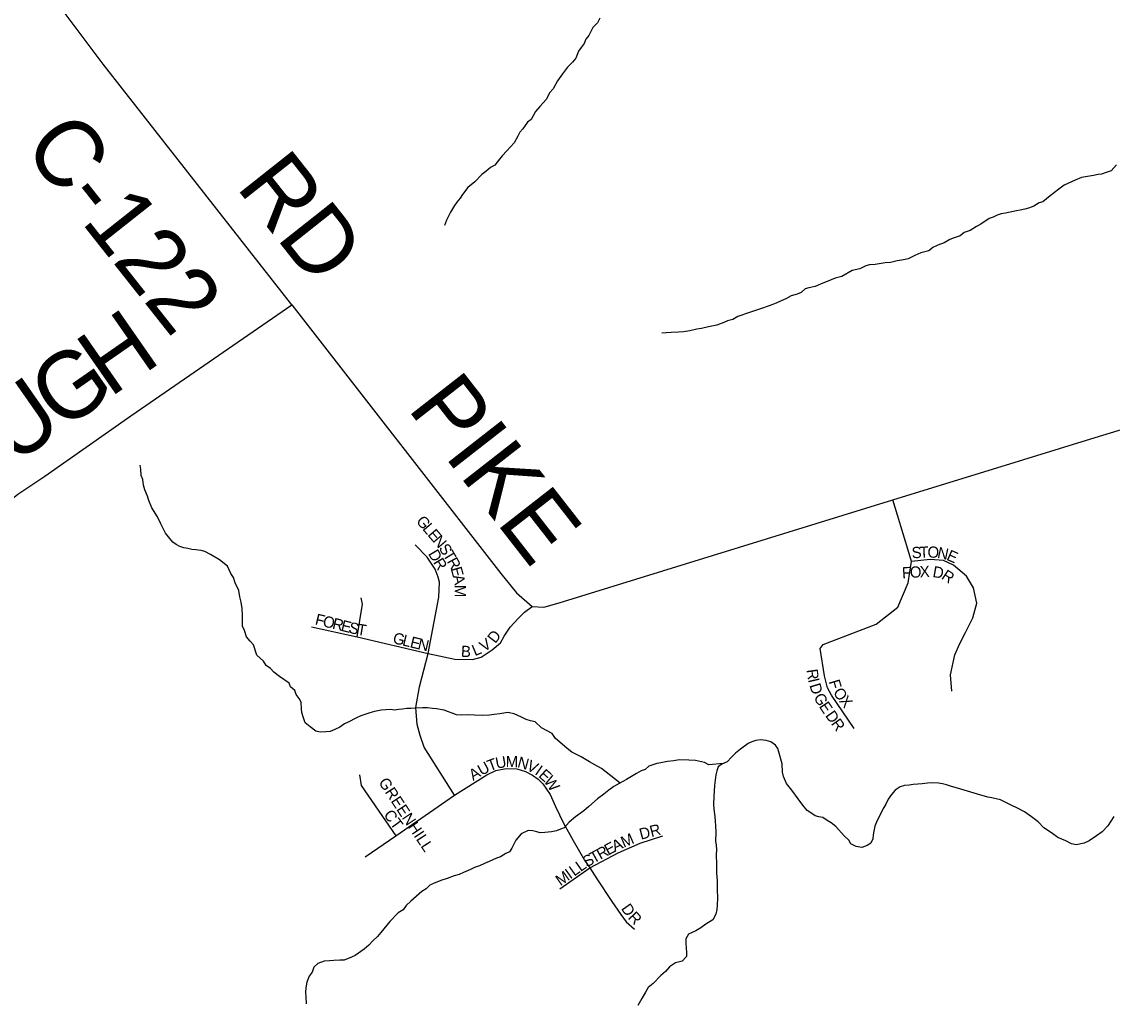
# Model space of a CAD drawing. Extents: x 1310247 to 1664935, y 235267 to 584339.
# Drawn here: x 1481596 to 1486473, y 391172 to 395560 of the extents above; entities that cross this region are included whole.
import ezdxf

# ---------------------------------------------------------------- set-up
doc = ezdxf.new("R2010")
doc.units = 0
for name, color, linetype in [('GM_X_County_Road', 7, 'Continuous'), ('GM_X_County_Road_Text', 7, 'Continuous'), ('GM_X_Minor_River', 7, 'Continuous'), ('GM_X_Township_Subdivision', 7, 'Continuous'), ('GM_X_Township_Subdivision_Text', 7, 'Continuous')]:
    doc.layers.add(name, color=color, linetype=linetype)

msp = doc.modelspace()

# ---------------------------------------------------------------- linework, layer by layer
at = {"layer": 'GM_X_County_Road'}
for points in [[(1482804.2, 394294.3), (1481959.6, 395370.7), (1480701.4, 397047.3), (1480675.9, 397086.6)], [(1479871.9, 391165.9), (1479912.2, 391215.7), (1479964.2, 391283.9), (1480390, 391862.6), (1480465.6, 391986.3), (1481093.8, 392839.4), (1481346.3, 393181.8), (1481456.2, 393329.1), (1481477.1, 393360.6), (1481522.2, 393401.5), (1481577.5, 393448.1), (1481699.6, 393529), (1482082.9, 393797.4), (1482804.2, 394294.3), (1483738.8, 393093.4), (1483807.8, 393007.3), (1483879.1, 392945.3), (1483931, 392942), (1483999.6, 392962.2), (1485491.8, 393422.4), (1486077.3, 393602.9), (1486397.1, 393700.6), (1486533.1, 393742.7)]]:
    msp.add_lwpolyline(points, dxfattribs=at)
at = {"layer": 'GM_X_Minor_River'}
for points in [[(1484180.9, 395575.8), (1484170.5, 395555.9), (1484150.1, 395534.2), (1484131.4, 395498.3), (1484119.1, 395482.5), (1484110.8, 395462.6), (1484098.4, 395444.7), (1484086.1, 395428.9), (1484073.5, 395397), (1484059.2, 395379.2), (1484036.7, 395357.5), (1484014.1, 395327.8), (1483991.5, 395296), (1483972.9, 395260.2), (1483956.5, 395242.5), (1483942, 395214.6), (1483913.3, 395181), (1483892.9, 395159.3), (1483874.2, 395123.5), (1483857.9, 395111.7), (1483837.4, 395081.9), (1483823.1, 395066.1), (1483814.7, 395048.2), (1483798.2, 395018.4), (1483781.8, 395000.6), (1483765.5, 394982.8), (1483745, 394961.1), (1483732.7, 394945.3), (1483712.2, 394919.5), (1483691.9, 394907.8), (1483671.6, 394890.1), (1483653.3, 394876.4), (1483622.6, 394844.8), (1483590.1, 394819.3), (1483567.5, 394787.6), (1483556.1, 394771.7), (1483542.3, 394754), (1483530.5, 394738), (1483513.9, 394708.2), (1483503.6, 394690.3), (1483496.1, 394672.6), (1483486.9, 394648.5)], [(1486492.4, 394921.1), (1486467.9, 394893.5), (1486445.7, 394885.8), (1486425.4, 394878.2), (1486409.4, 394876.4), (1486389.2, 394872.8), (1486353, 394867.4), (1486334.9, 394863.7), (1486306.6, 394852.1), (1486258, 394828.9), (1486233.6, 394811.2), (1486195, 394781.8), (1486162.4, 394754.3), (1486146.3, 394750.5), (1486121.9, 394734.9), (1486097.7, 394727.3), (1486081.6, 394721.6), (1486061.4, 394717.9), (1486045.3, 394714.2), (1485995, 394705), (1485976.8, 394701.3), (1485958.7, 394695.6), (1485940.4, 394685.9), (1485922.3, 394680.2), (1485885.7, 394654.7), (1485865.5, 394645), (1485837.1, 394627.5), (1485810.8, 394617.9), (1485792.5, 394602.2), (1485766.3, 394594.6), (1485746.1, 394586.9), (1485721.7, 394571.3), (1485693.5, 394561.8), (1485671.2, 394550.1), (1485652.9, 394536.4), (1485616.6, 394527), (1485590.3, 394515.4), (1485559.9, 394499.8)], [(1485559.9, 394499.8), (1485539.8, 394496.2), (1485511.6, 394490.7), (1485481.4, 394483.1), (1485457.3, 394481.6), (1485439.2, 394479.9), (1485413, 394474.3), (1485386.9, 394472.8), (1485370.7, 394469), (1485344.4, 394455.4), (1485310.2, 394448), (1485263.5, 394420.7), (1485233.3, 394413.2), (1485215.1, 394405.5), (1485168.6, 394386.3), (1485144.4, 394376.6), (1485116.2, 394371.1), (1485100, 394365.4), (1485081.7, 394349.6), (1485063.5, 394341.9), (1485037.3, 394334.3), (1485012.9, 394320.7), (1484992.7, 394313), (1484970.5, 394301.4), (1484938.2, 394289.9), (1484903.8, 394278.5), (1484877.6, 394268.9), (1484833.2, 394253.6), (1484817, 394247.9), (1484798.8, 394242.2), (1484776.5, 394228.5), (1484752.4, 394222.9), (1484736.2, 394215.2), (1484703.9, 394203.7), (1484667.6, 394196.3), (1484635.4, 394188.8), (1484615.2, 394185.2), (1484583, 394177.7), (1484554.8, 394174.2), (1484532.7, 394172.6), (1484500.6, 394171.1), (1484478.5, 394169.5), (1484458.4, 394167.8)], [(1482176.9, 393386.8), (1482163.4, 393419.1), (1482157.7, 393439.3), (1482146.2, 393467.6), (1482140.5, 393487.8), (1482136.9, 393513.9), (1482129.2, 393532.1), (1482127.7, 393560.2), (1482126, 393578.3)], [(1484272.6, 392156.5), (1484188.8, 392221.6), (1484159, 392238.2), (1484135.1, 392250.7), (1484097.4, 392273.4), (1484079.4, 392281.8), (1484055.6, 392294.2), (1484035.8, 392310.6), (1484002.1, 392339.3), (1483982.3, 392355.7), (1483968.6, 392378), (1483920.9, 392403), (1483891.2, 392429.6), (1483871.2, 392433.9), (1483851.2, 392440.3), (1483831.3, 392450.7), (1483797.5, 392465.3), (1483769.5, 392471.8), (1483751.3, 392468.1), (1483733.3, 392466.5), (1483709.1, 392462.9), (1483687, 392459.2), (1483656.8, 392457.8), (1483620.7, 392460.4), (1483590.6, 392460.9), (1483564.5, 392459.4), (1483540.5, 392461.8), (1483520.5, 392468.2), (1483504.6, 392474.5), (1483484.6, 392482.8), (1483450.6, 392487.5), (1483432.5, 392489.8), (1483410.5, 392492.2), (1483388.4, 392492.5), (1483356.3, 392491.1), (1483336.2, 392489.5), (1483318.1, 392489.8), (1483298, 392486.1), (1483281.9, 392484.4), (1483261.8, 392482.7), (1483245.8, 392485), (1483223.7, 392483.4), (1483203.6, 392481.8), (1483173.4, 392476.2), (1483153.2, 392470.6), (1483112.8, 392457.2), (1483092.6, 392447.6), (1483056.1, 392428.1), (1483039.9, 392420.4), (1483017.6, 392406.7), (1482995.4, 392395.1), (1482975.2, 392387.4), (1482955.1, 392385.7), (1482930.9, 392384.2), (1482910.9, 392388.5), (1482885.2, 392407), (1482863.4, 392425.5), (1482853.8, 392451.7), (1482848.1, 392471.9), (1482846.4, 392488), (1482844.9, 392518.1), (1482837.1, 392534.3), (1482823.4, 392552.6), (1482817.6, 392570.8), (1482797.9, 392587.2), (1482792.1, 392603.3), (1482748.4, 392632.2), (1482722.7, 392652.7), (1482708.9, 392669), (1482689, 392681.4), (1482677.3, 392701.7), (1482647.7, 392728.3), (1482632.4, 392774.7), (1482616.6, 392791), (1482600.8, 392809.4), (1482591.3, 392837.7), (1482583.6, 392857.9), (1482582.4, 392906), (1482580.9, 392936.2), (1482577.3, 392964.3), (1482571.7, 392988.5), (1482566.2, 393016.7), (1482550.7, 393051.1), (1482543.1, 393075.3), (1482531.3, 393093.6), (1482515.8, 393126), (1482480.2, 393154.7), (1482440.4, 393177.5), (1482414.5, 393192), (1482398.6, 393196.3), (1482374.5, 393198.7), (1482356.5, 393201), (1482338.5, 393205.3), (1482320.5, 393207.7), (1482302.5, 393214), (1482286.6, 393222.3), (1482270.7, 393232.6), (1482239.3, 393273.3), (1482217.9, 393315.8), (1482202.4, 393346.2), (1482176.9, 393386.8)], [(1486479.6, 392006.9), (1486452.8, 391965.2), (1486428.3, 391937.5), (1486401.9, 391919.9), (1486369.4, 391898.4), (1486347.1, 391886.8), (1486310.9, 391879.4), (1486290.9, 391883.8), (1486265, 391898.3), (1486229.1, 391912.9), (1486201.4, 391933.5), (1486167.6, 391956.2), (1486142, 391982.7), (1486112.2, 392005.3), (1486080.5, 392027.9), (1486048.7, 392044.5), (1486020.8, 392057.1), (1485973, 392082), (1485935, 392090.7), (1485917, 392093), (1485871, 392105.9), (1485795.2, 392129.3), (1485749.2, 392142.1), (1485731.2, 392148.5), (1485713.3, 392152.8), (1485695.2, 392155.1), (1485669.2, 392157.6), (1485647.1, 392156), (1485622.9, 392152.4), (1485602.8, 392150.7), (1485582.7, 392149.1), (1485564.6, 392147.4), (1485544.5, 392145.7), (1485524.3, 392140), (1485502, 392124.4), (1485485.6, 392104.6), (1485471.2, 392084.8), (1485458.8, 392058.9), (1485448.4, 392043), (1485436, 392017.2), (1485421.4, 391989.3), (1485411, 391963.4), (1485406.6, 391941.4), (1485404.3, 391925.4), (1485402, 391907.4), (1485393.6, 391887.4), (1485377.4, 391877.7), (1485353.2, 391868.1), (1485327.1, 391872.5), (1485303.3, 391885), (1485295.5, 391901.2), (1485273.7, 391919.6), (1485236.3, 391962.4), (1485216.5, 391978.9), (1485198.6, 391989.2), (1485178.8, 392001.6), (1485160.8, 392005.9), (1485144.8, 392010.2), (1485124.9, 392022.6), (1485109, 392032.9), (1485089.4, 392057.3), (1485067.8, 392085.8), (1485040.3, 392124.4), (1485016.7, 392155), (1485003.2, 392185.3), (1484997.5, 392205.5), (1484996.1, 392241.6), (1484982.9, 392290), (1484977.2, 392310.2), (1484967.4, 392326.4), (1484945.6, 392340.8), (1484925.6, 392347.2), (1484901.6, 392349.7), (1484879.4, 392346), (1484861.3, 392340.3), (1484845.1, 392332.6)], [(1484845.1, 392332.6), (1484810.5, 392307.1), (1484788.2, 392289.4), (1484769.8, 392271.7), (1484751.4, 392251.9), (1484727.1, 392240.3), (1484710.9, 392228.6), (1484704.5, 392210.6), (1484700.2, 392192.6), (1484693.4, 392144.6), (1484690.6, 392096.5), (1484690, 392062.3), (1484691.6, 392040.2), (1484695.1, 392006), (1484696.8, 391988), (1484698.4, 391963.8), (1484700, 391937.7), (1484699.2, 391895.6), (1484701, 391879.5), (1484702.6, 391857.4), (1484702.2, 391835.3), (1484703.6, 391793.2), (1484702.9, 391753), (1484706.3, 391720.8), (1484705.6, 391676.7), (1484707.1, 391644.6), (1484706.5, 391608.5), (1484704.2, 391590.4), (1484699.8, 391570.4), (1484687.3, 391544.6), (1484654.9, 391525.1), (1484632.5, 391509.4), (1484610.2, 391495.8), (1484577.9, 391480.2), (1484565.5, 391460.4), (1484565.2, 391442.3), (1484566.8, 391418.2), (1484568.5, 391400.1), (1484568.2, 391380.1), (1484549.8, 391360.3), (1484519.5, 391352.8), (1484493.1, 391335.2), (1484474.7, 391313.5), (1484454.3, 391295.8), (1484419.6, 391260.2), (1484397.2, 391242.6), (1484384.8, 391220.7), (1484368.3, 391192.9), (1484351.7, 391161.1)], [(1484733.1, 392243.2), (1484668.8, 392237.3), (1484648.9, 392247.7), (1484608.9, 392256.4), (1484578.9, 392259), (1484536.7, 392259.7), (1484512.6, 392256.1), (1484484.4, 392252.6), (1484454.2, 392247.1), (1484436.1, 392243.4), (1484399.8, 392232), (1484383.5, 392216.2), (1484365.3, 392210.5), (1484345, 392198.8), (1484300.4, 392171.5), (1484268, 392154), (1484243.7, 392140.4), (1484221.3, 392124.7), (1484199, 392107.1), (1484170.5, 392085.5), (1484131.8, 392052), (1484109.4, 392032.4), (1484072.8, 392004.9), (1484044.3, 391981.3), (1484021.8, 391955.6), (1484005.6, 391949.9), (1483987.4, 391942.2), (1483965.3, 391938.5), (1483935.1, 391935.1), (1483915, 391933.4), (1483899, 391937.7), (1483881, 391942), (1483861, 391944.4), (1483828.6, 391928.9), (1483806.1, 391901.2), (1483787.4, 391865.4), (1483777.1, 391849.5), (1483760.9, 391841.8), (1483736.6, 391826.2), (1483718.4, 391820.5), (1483686, 391805), (1483665.8, 391797.3), (1483643.5, 391785.6), (1483621.3, 391778), (1483603.1, 391770.3), (1483570.8, 391756.8), (1483552.6, 391747.1), (1483530.4, 391741.5), (1483498.1, 391730), (1483473.9, 391722.4), (1483439.5, 391708.9), (1483421.3, 391699.2), (1483405, 391683.5), (1483384.7, 391671.8), (1483335.8, 391628.5), (1483315.4, 391608.8), (1483301, 391588.9), (1483278.7, 391575.3), (1483241.9, 391537.8), (1483201, 391488.3), (1483186.6, 391470.5), (1483166.2, 391450.8), (1483147.8, 391431.1), (1483127.4, 391413.4), (1483086.8, 391386), (1483070.6, 391378.2), (1483038.3, 391364.8), (1483018.2, 391365.1), (1482992.1, 391363.5), (1482972, 391361.9), (1482947.9, 391360.3), (1482919.6, 391348.8), (1482901.3, 391333), (1482894.9, 391311.1), (1482880.5, 391293.3), (1482870, 391265.3), (1482865.6, 391241.3), (1482865.3, 391221.3), (1482866.9, 391201.2), (1482868.4, 391169)]]:
    msp.add_lwpolyline(points, dxfattribs=at)
at = {"layer": 'GM_X_Township_Subdivision'}
for points in [[(1485558.7, 393202.5), (1485491.8, 393422.4)], [(1483413.1, 392735.1), (1483460.5, 392986.7), (1483464.7, 393054.8), (1483458.5, 393077.5), (1483444, 393112.5), (1483409, 393166.1), (1483355.4, 393221.8)], [(1485318.3, 392400.3), (1485217.2, 392549.7), (1485199.6, 392582.7), (1485186.4, 392635.4), (1485166.6, 392758.5), (1485179.8, 392776.1), (1485417.2, 392866.2), (1485513.9, 392943.1), (1485560, 393050.8), (1485575.4, 393147.5), (1485558.7, 393202.5)], [(1485755.6, 392567.3), (1485749, 392639.8), (1485768.8, 392729.9), (1485790.8, 392780.5), (1485817.2, 392828.8), (1485850.1, 392894.8), (1485867.7, 392960.7), (1485852.3, 393028.8), (1485821.6, 393081.6), (1485762.2, 393129.9), (1485718.3, 393151.9), (1485658.9, 393156.3), (1485575.4, 393147.5)], [(1483095.5, 392809.4), (1483120.1, 392955.5), (1483114, 392984.6)], [(1482891.4, 392854.7), (1483095.5, 392809.4), (1483413.1, 392735.1), (1483532.7, 392710.4), (1483611.1, 392708.3), (1483650.2, 392718.6), (1483699.8, 392751.6), (1483736.9, 392782.5), (1483753.4, 392813.5), (1483780.2, 392852.7), (1483815.2, 392891.9), (1483844.1, 392920.7), (1483879.1, 392945.3)], [(1483530.7, 392102.8), (1483394.8, 392317.3), (1483377.1, 392369.4), (1483364.4, 392417.6), (1483358, 392493.8), (1483374.5, 392586.4), (1483413.1, 392735.1)], [(1483105.6, 392192.5), (1483114.3, 392144.7), (1483268.2, 391921)], [(1483132.1, 391826.1), (1483268.2, 391921), (1483530.7, 392102.8), (1483675.3, 392193), (1483716, 392212), (1483761.6, 392220.9), (1483809.9, 392219.6), (1483849.2, 392208.2), (1483879.7, 392191.7), (1483905.1, 392173.9), (1483926.7, 392152.3), (1483958.4, 392105.4), (1483982.5, 392052.1), (1484018, 391977.2), (1484061.2, 391899.8), (1484112, 391810.9), (1484136.1, 391776.7), (1484167.8, 391728.4), (1484235.1, 391626.9), (1484275.7, 391568.5), (1484299.6, 391535.4), (1484336.6, 391502.5)], [(1484002.5, 391683), (1484136.1, 391776.7), (1484262.7, 391843.6), (1484362.3, 391887.4), (1484462.6, 391919.8)]]:
    msp.add_lwpolyline(points, dxfattribs=at)

# ---------------------------------------------------------------- texts
at = {"layer": 'GM_X_County_Road_Text'}
for s, rotation, p in [('C-122', 308.3591, (1481595.9, 394997.6)), ('RD', 308.3509, (1482550.3, 394822.2)), ('H', 34.8323, (1481988.8, 393876.6)), ('G', 34.8338, (1481772.1, 393725.8)), ('U', 34.9126, (1481555.7, 393574.8)), ('PIKE', 307.9831, (1483316.5, 393831.7))]:
    msp.add_text(s, height=300, rotation=rotation, dxfattribs=at).set_placement(p)
at = {"layer": 'GM_X_Township_Subdivision_Text'}
for s, rotation, p in [('G', 310.4828, (1483356.8, 393325.5)), ('L', 310.4738, (1483385.4, 393292)), ('E', 310.4651, (1483408.3, 393265.3)), ('N', 310.4766, (1483431.1, 393238.5)), ('S', 303.0915, (1483458.7, 393206.3)), ('S', 2.5418, (1485576.8, 393161.2)), ('T', 2.5418, (1485612, 393162.8)), ('O', 358.776, (1485646.3, 393164.3)), ('N', 348.27, (1485687.8, 393163.7)), ('D', 300.4877, (1483411.6, 393181.7)), ('R', 300.9714, (1483434.1, 393143.4)), ('T', 301.1512, (1483477.6, 393177.2)), ('R', 298.6938, (1483495.6, 393147.6)), ('E', 336.0015, (1485728.2, 393155.6)), ('E', 285.6265, (1483513.4, 393115.6)), ('F', 3.7995, (1485534.1, 393071)), ('O', 3.6745, (1485569.2, 393073.3)), ('X', 2.2303, (1485612.8, 393076.1)), ('D', 349.7616, (1485667.1, 393078.1)), ('A', 282.5834, (1483522.8, 393082.4)), ('R', 326.4986, (1485705.4, 393072.3)), ('M', 270, (1483532, 393042.4)), ('F', 346.1493, (1482904.5, 392866.2)), ('O', 346.1694, (1482938.7, 392857.7)), ('R', 346.1801, (1482981.5, 392847.2)), ('E', 346.1493, (1483019.9, 392837.7)), ('S', 346.1682, (1483054.1, 392829.3)), ('T', 350.6768, (1483092.5, 392820)), ('G', 346.3878, (1483252.1, 392782.6)), ('D', 52.7095, (1483713.7, 392777.4)), ('L', 346.3746, (1483294.8, 392772.2)), ('E', 346.3746, (1483329, 392763.9)), ('N', 346.9288, (1483363.7, 392755.5)), ('L', 22.6943, (1483622.2, 392723)), ('V', 32.8062, (1483663.1, 392741)), ('B', 356.7191, (1483558.9, 392721.2)), ('R', 278.2606, (1485105.4, 392662.5)), ('I', 283.0575, (1485112, 392618.8)), ('D', 286.9745, (1485117.9, 392593.7)), ('F', 286.5946, (1485204.3, 392610.6)), ('O', 305.1805, (1485222, 392561)), ('G', 299.7017, (1485135.5, 392540.5)), ('X', 307.7794, (1485248.8, 392523)), ('E', 303.9897, (1485159.5, 392498.9)), ('D', 305.2616, (1485187.4, 392457.9)), ('R', 305.3694, (1485212.9, 392421.9)), ('U', 28.5006, (1483651.5, 392187.9)), ('T', 20.5433, (1483688.5, 392208.1)), ('U', 10.5941, (1483719.3, 392219.8)), ('M', 359.4354, (1483760, 392227.7)), ('N', 344.4689, (1483809.4, 392227.7)), ('V', 333.347, (1483849.4, 392216.8)), ('A', 31.1436, (1483614.4, 392165.4)), ('I', 325.0366, (1483887.1, 392198.1)), ('E', 317.9377, (1483903.8, 392186.5)), ('W', 305.3364, (1483928, 392165.1)), ('GREENHILL', 303.4847, (1483189.4, 392159.7)), ('CT', 306.2589, (1483211.9, 392014.3)), ('DR', 14.7487, (1484365, 391902.5)), ('E', 28.4229, (1484218.3, 391831.7)), ('A', 24.9522, (1484248.5, 391848)), ('M', 23.2727, (1484288.1, 391866.5)), ('T', 29.0095, (1484152.9, 391795.6)), ('R', 28.781, (1484183.6, 391812.6)), ('L', 34.804, (1484095, 391758)), ('S', 31.0669, (1484123.2, 391777.7)), ('M', 35.4636, (1484005.5, 391694.3)), ('I', 35.5058, (1484048.6, 391724.9)), ('L', 35.471, (1484066.5, 391737.7)), ('D', 305.1693, (1484274.2, 391594.8)), ('R', 313.6634, (1484304.6, 391552.7))]:
    msp.add_text(s, height=50, rotation=rotation, dxfattribs=at).set_placement(p)

doc.saveas('drawing.dxf')
